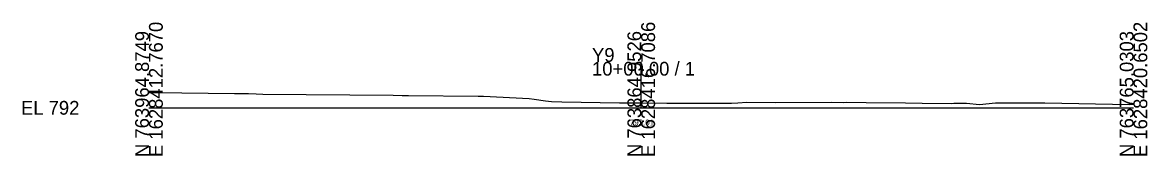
# Model space of a CAD drawing. Extents: x -26 to 203, y -10 to 6017.
# Drawn here: x -25.7 to 202.8, y -9.7 to 17.3 of the extents above; entities that cross this region are included whole.
import ezdxf

# ---------------------------------------------------------------- set-up
doc = ezdxf.new("R2010")
doc.units = 0
for name, color, linetype in [('Default', 7, 'Continuous'), ('Exist Cross Section Cell', 7, 'Continuous'), ('Exist XS Center Line Elevation Label', 7, 'Continuous'), ('Exist XS Ground Line', 7, 'Continuous')]:
    doc.layers.add(name, color=color, linetype=linetype)

msp = doc.modelspace()

# ---------------------------------------------------------------- linework, layer by layer
at = {"layer": 'Exist Cross Section Cell'}
for p, q in [((100, 0), (100, 9.34)), ((0, 0), (100, 0)), ((100, 0), (200, 0))]:
    msp.add_line(p, q, dxfattribs=at)
at = {"layer": 'Exist XS Ground Line'}
msp.add_lwpolyline([(0, 3.11), (1.3, 3.1), (17.34, 2.9), (17.71, 2.9), (18.2, 2.91), (18.72, 2.91), (19.34, 2.9), (20.21, 2.88), (21.76, 2.82), (23.15, 2.75), (49.61, 2.55), (51.41, 2.53), (52.71, 2.52), (66.87, 2.38), (67.94, 2.38), (77.2, 1.9), (78.26, 1.78), (80.58, 1.45), (81.75, 1.26), (83.84, 1.22), (95.6, 1.01), (98.02, 1.03), (100, 1.01), (105.2, 0.94), (118.32, 0.91), (119.62, 1), (121.43, 1.12), (127.29, 1.08), (138.67, 1.13), (141.04, 1.05), (141.64, 1.13), (145.71, 1.11), (153.69, 0.98), (157.09, 0.95), (163.07, 0.9), (163.49, 0.92), (166.07, 0.95), (168.72, 0.69), (171.93, 0.99), (175.11, 1.02), (181.96, 0.98), (199.2, 0.7), (200, 0.72)], dxfattribs=at)

# ---------------------------------------------------------------- texts
at = {"layer": 'Default'}
msp.add_text('-', height=0.0001, dxfattribs=at).set_placement((0, 0))
at = {"layer": 'Exist Cross Section Cell'}
for s, p in [('E 1628412.7670', (2.8, -10)), ('E 1628416.7086', (102.8, -10)), ('E 1628420.6502', (202.8, -10)), ('N 763964.8749', (0, -10)), ('N 763864.9526', (100, -10)), ('N 763765.0303', (200, -10))]:
    msp.add_text(s, height=2.8, rotation=90, dxfattribs=at).set_placement(p)
for s, p in [('Y9', (90, 9.34)), ('10+00.00 / 1', (90, 6.54)), ('EL 792', (-26, -1.4))]:
    msp.add_text(s, height=2.8, dxfattribs=at).set_placement(p)
at = {"layer": 'Exist XS Center Line Elevation Label'}
msp.add_text('793.01', height=1.2, dxfattribs=at).set_placement((97.69, -3.59))

doc.saveas('drawing.dxf')
